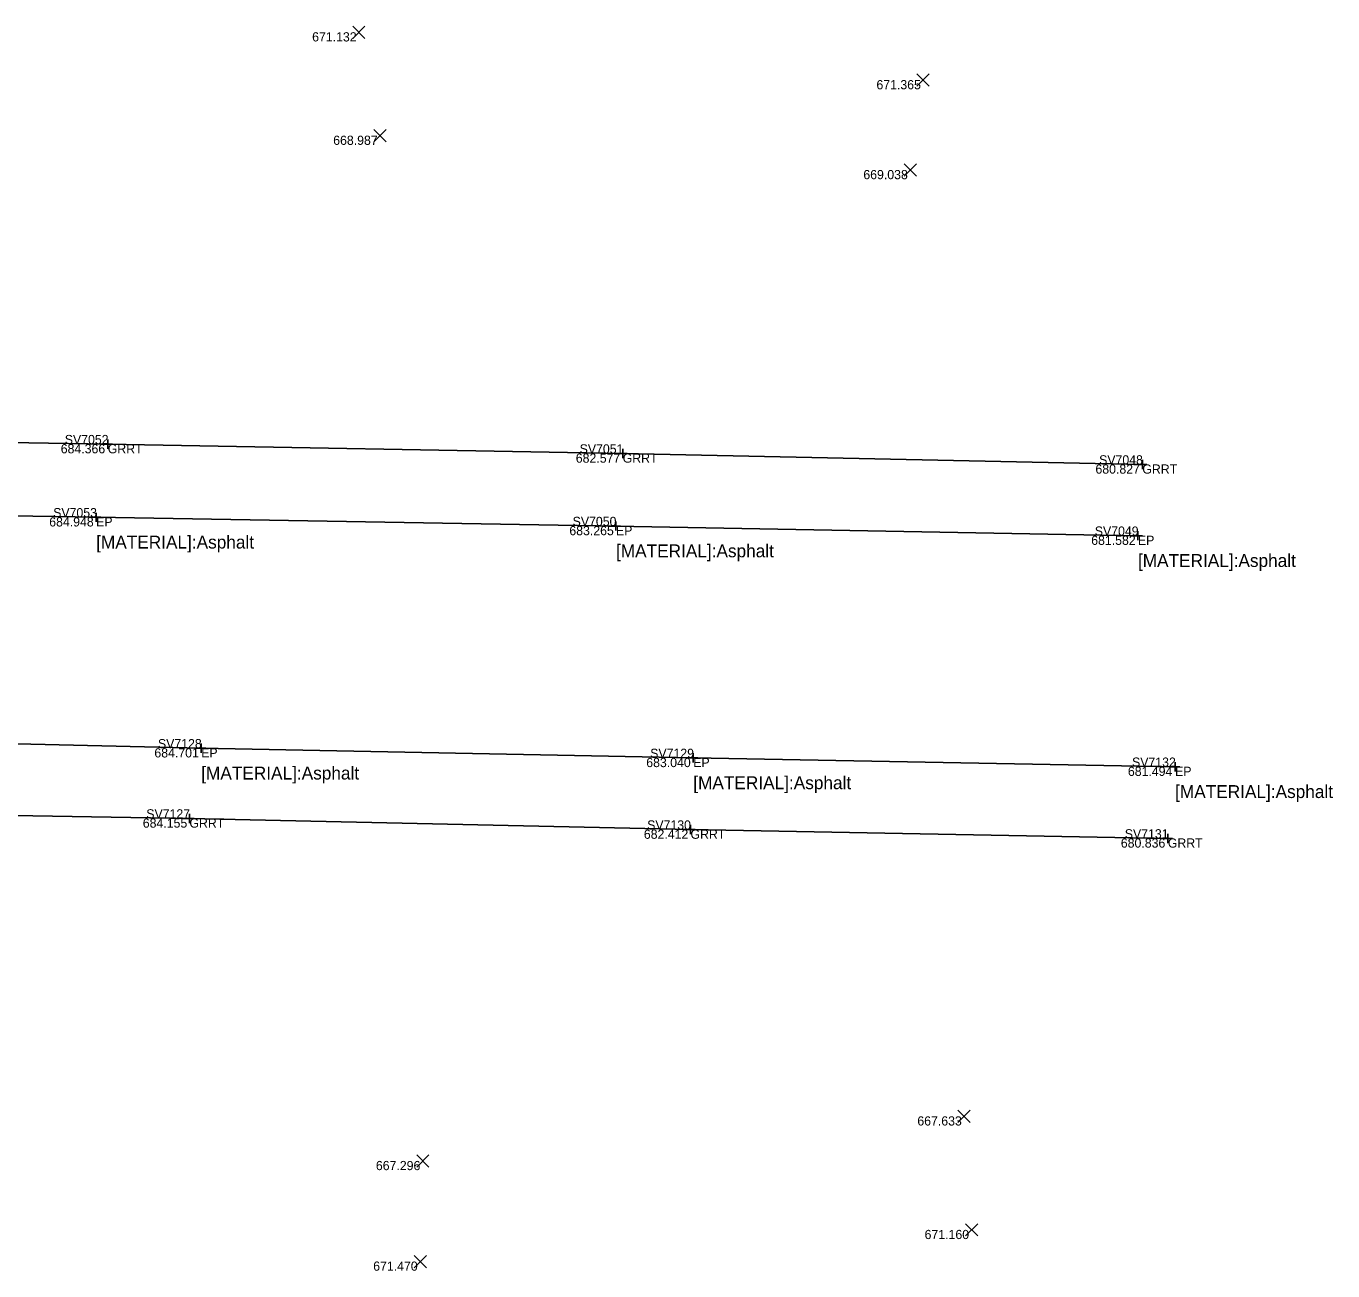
# Model space of a CAD drawing. Extents: x 1660019 to 1662995, y 619975 to 620342.
# Drawn here: x 1661990.8 to 1662132.9, y 620149.4 to 620284.7 of the extents above; entities that cross this region are included whole.
import ezdxf

# ---------------------------------------------------------------- set-up
doc = ezdxf.new("R2010")
doc.units = 0
for name, color, linetype in [('BR_X_Rail_Object', 7, 'Continuous'), ('PV_X_EOP', 7, 'Continuous'), ('RD_P_GR_Lt', 7, 'Continuous'), ('RD_P_GR_Rt', 7, 'Continuous'), ('RD_X_GR_Bar', 7, 'Continuous'), ('RD_X_GR_Rt', 7, 'Continuous'), ('RD_X_Wall', 7, 'Continuous'), ('SV_X_Text', 7, 'Continuous')]:
    doc.layers.add(name, color=color, linetype=linetype)

msp = doc.modelspace()

# ---------------------------------------------------------------- linework, layer by layer
at = {"layer": 'PV_X_EOP'}
for points in [[(1662111.67, 620229.32), (1662054.93, 620230.37), (1661998.42, 620231.32), (1661945.73, 620232.16), (1661885.47, 620233.5), (1661831.11, 620234.65), (1661773.24, 620235.9), (1661719.2, 620236.82), (1661662.34, 620238.11), (1661602.46, 620239.35), (1661551.29, 620241.52)], [(1661543.6, 620215.08), (1661595.45, 620214.35), (1661653.94, 620213.41), (1661707.72, 620212.24), (1661760.97, 620211.02), (1661840.69, 620209.32), (1661897.28, 620208.31), (1661955.8, 620207.5), (1662009.84, 620206.22), (1662063.33, 620205.17), (1662115.71, 620204.21)]]:
    msp.add_lwpolyline(points, dxfattribs=at)
at = {"layer": 'RD_P_GR_Lt'}
for p, q in [((1661999.68, 620239.77), (1661999.68, 620238.77)), ((1661999.18, 620239.27), (1662000.18, 620239.27)), ((1661999.68, 620239.27), (1661999.68, 620239.27)), ((1662055.66, 620238.75), (1662055.66, 620237.75)), ((1662055.16, 620238.25), (1662056.16, 620238.25)), ((1662055.66, 620238.25), (1662055.66, 620238.25)), ((1662111.65, 620237.06), (1662112.65, 620237.06)), ((1662112.15, 620237.56), (1662112.15, 620236.56)), ((1662112.15, 620237.06), (1662112.15, 620237.06)), ((1661997.92, 620231.32), (1661998.92, 620231.32)), ((1661998.42, 620231.82), (1661998.42, 620230.82)), ((1661998.42, 620231.32), (1661998.42, 620231.32)), ((1662054.43, 620230.37), (1662055.43, 620230.37)), ((1662054.93, 620230.87), (1662054.93, 620229.87)), ((1662054.93, 620230.37), (1662054.93, 620230.37)), ((1662111.67, 620229.82), (1662111.67, 620228.82)), ((1662111.17, 620229.32), (1662112.17, 620229.32)), ((1662111.67, 620229.32), (1662111.67, 620229.32)), ((1662009.34, 620206.22), (1662010.34, 620206.22)), ((1662009.84, 620206.72), (1662009.84, 620205.72)), ((1662009.84, 620206.22), (1662009.84, 620206.22)), ((1662063.33, 620205.67), (1662063.33, 620204.67)), ((1662062.83, 620205.17), (1662063.83, 620205.17)), ((1662063.33, 620205.17), (1662063.33, 620205.17)), ((1662115.71, 620204.71), (1662115.71, 620203.71)), ((1662115.21, 620204.21), (1662116.21, 620204.21)), ((1662115.71, 620204.21), (1662115.71, 620204.21)), ((1662008.06, 620198.59), (1662009.06, 620198.59)), ((1662008.56, 620199.09), (1662008.56, 620198.09)), ((1662008.56, 620198.59), (1662008.56, 620198.59)), ((1662062.53, 620197.38), (1662063.53, 620197.38)), ((1662063.03, 620197.88), (1662063.03, 620196.88)), ((1662063.03, 620197.38), (1662063.03, 620197.38)), ((1662114.42, 620196.42), (1662115.42, 620196.42)), ((1662114.92, 620196.92), (1662114.92, 620195.92)), ((1662114.92, 620196.42), (1662114.92, 620196.42))]:
    msp.add_line(p, q, dxfattribs=at)
at = {"layer": 'RD_P_GR_Rt'}
for p, q in [((1662026.31, 620283.36), (1662027.64, 620284.69)), ((1662026.31, 620284.69), (1662027.64, 620283.36)), ((1662087.64, 620278.16), (1662088.98, 620279.5)), ((1662087.64, 620279.5), (1662088.98, 620278.16)), ((1662028.62, 620272.12), (1662029.95, 620273.45)), ((1662028.62, 620273.45), (1662029.95, 620272.12)), ((1662086.25, 620268.39), (1662087.58, 620269.73)), ((1662086.25, 620269.73), (1662087.58, 620268.39)), ((1662092.09, 620165.55), (1662093.42, 620166.88)), ((1662092.09, 620166.88), (1662093.42, 620165.55)), ((1662033.27, 620160.7), (1662034.6, 620162.03)), ((1662033.27, 620162.03), (1662034.6, 620160.7)), ((1662092.93, 620153.22), (1662094.26, 620154.55)), ((1662092.93, 620154.55), (1662094.26, 620153.22)), ((1662032.98, 620149.77), (1662034.32, 620151.11)), ((1662032.98, 620151.11), (1662034.32, 620149.77))]:
    msp.add_line(p, q, dxfattribs=at)
at = {"layer": 'RD_X_GR_Rt'}
for points in [[(1662112.15, 620237.06), (1662055.66, 620238.25), (1661999.68, 620239.27), (1661943.73, 620240.2), (1661887.33, 620241.47), (1661831.01, 620242.22), (1661774.89, 620243.8), (1661718.6, 620244.37), (1661662.44, 620245.38), (1661601.89, 620244.64), (1661537.84, 620244.62)], [(1661527.71, 620211.76), (1661596.63, 620209.07), (1661652.77, 620205.71), (1661709.09, 620204.45), (1661758.9, 620203.47), (1661840.54, 620201.81), (1661896.27, 620200.97), (1661955.33, 620199.48), (1662008.56, 620198.59), (1662063.03, 620197.38), (1662114.92, 620196.42)]]:
    msp.add_lwpolyline(points, dxfattribs=at)

# ---------------------------------------------------------------- texts
at = {"layer": 'BR_X_Rail_Object'}
for s, p in [('GRRT', (1661999.68, 620238.27)), ('GRRT', (1662055.66, 620237.25)), ('GRRT', (1662112.15, 620236.06)), ('EP', (1661998.42, 620230.32)), ('EP', (1662054.93, 620229.37)), ('EP', (1662111.67, 620228.32)), ('EP', (1662009.84, 620205.22)), ('EP', (1662063.33, 620204.17)), ('EP', (1662115.71, 620203.21)), ('GRRT', (1662008.56, 620197.59)), ('GRRT', (1662063.03, 620196.38)), ('GRRT', (1662114.92, 620195.42))]:
    msp.add_text(s, height=1, dxfattribs=at).set_placement(p)
at = {"layer": 'RD_X_GR_Bar'}
for s, p in [('671.132', (1662021.9, 620283.03)), ('671.365', (1662083.24, 620277.83)), ('668.987', (1662024.19, 620271.79)), ('669.038', (1662081.82, 620268.06)), ('684.366', (1661994.57, 620238.27)), ('682.577', (1662050.56, 620237.25)), ('680.827', (1662107.05, 620236.06)), ('684.948', (1661993.32, 620230.32)), ('683.265', (1662049.86, 620229.37)), ('681.582', (1662106.59, 620228.32)), ('684.701', (1662004.75, 620205.22)), ('683.040', (1662058.22, 620204.17)), ('681.494', (1662110.58, 620203.21)), ('684.155', (1662003.49, 620197.59)), ('682.412', (1662057.96, 620196.38)), ('680.836', (1662109.81, 620195.42)), ('667.633', (1662087.69, 620165.22)), ('667.296', (1662028.83, 620160.37)), ('671.160', (1662088.48, 620152.88)), ('671.470', (1662028.54, 620149.44))]:
    msp.add_text(s, height=1, dxfattribs=at).set_placement(p)
at = {"layer": 'RD_X_Wall'}
for s, p in [('SV7052', (1661995.01, 620239.27)), ('SV7051', (1662050.98, 620238.25)), ('SV7048', (1662107.45, 620237.06)), ('SV7053', (1661993.75, 620231.32)), ('SV7050', (1662050.22, 620230.37)), ('SV7049', (1662106.98, 620229.32)), ('SV7128', (1662005.14, 620206.22)), ('SV7129', (1662058.65, 620205.17)), ('SV7132', (1662111.03, 620204.21)), ('SV7127', (1662003.87, 620198.59)), ('SV7130', (1662058.32, 620197.38)), ('SV7131', (1662110.24, 620196.42))]:
    msp.add_text(s, height=1, dxfattribs=at).set_placement(p)
at = {"layer": 'SV_X_Text'}
for p in [(1661998.42, 620227.92), (1662054.93, 620226.97), (1662111.67, 620225.92), (1662009.84, 620202.82), (1662063.33, 620201.77), (1662115.71, 620200.81)]:
    msp.add_text('[MATERIAL]:Asphalt', height=1.4, dxfattribs=at).set_placement(p)

doc.saveas('drawing.dxf')
